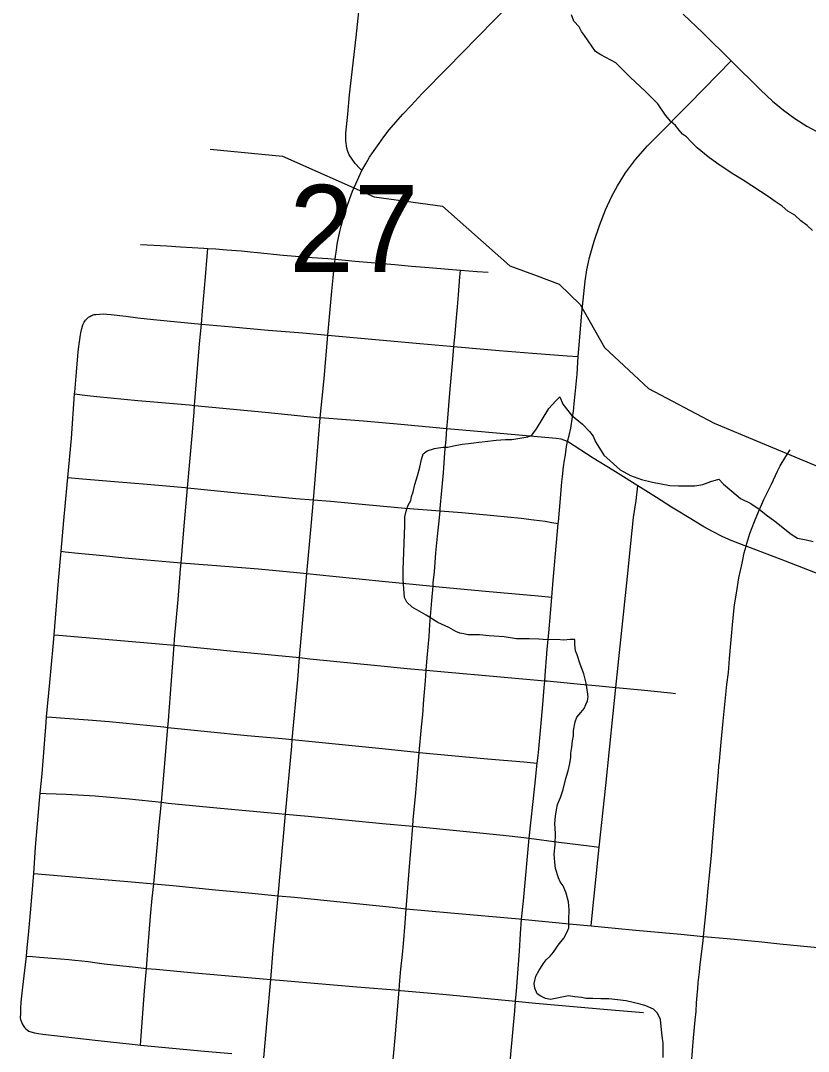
# Model space of a CAD drawing. Extents: x 0 to 34, y 0 to 22.
# Drawn here: x 25.5076 to 25.8867, y 17.7977 to 18.2936 of the extents above; entities that cross this region are included whole.
import ezdxf

# ---------------------------------------------------------------- set-up
doc = ezdxf.new("R2010")
doc.units = 0
for name, color, linetype in [('GM_X_City_Street', 7, 'Continuous'), ('GM_X_County_Road', 7, 'Continuous'), ('GM_X_Minor_River', 7, 'Continuous'), ('GM_X_Section_Text', 7, 'Continuous'), ('GM_X_State_Route', 7, 'Continuous')]:
    doc.layers.add(name, color=color, linetype=linetype)

msp = doc.modelspace()

# ---------------------------------------------------------------- linework, layer by layer
at = {"layer": 'GM_X_City_Street'}
for points in [[(25.67191, 18.22143), (25.67093, 18.22249), (25.66867, 18.22491), (25.66717, 18.22691), (25.66578, 18.22908), (25.66506, 18.2306), (25.66457, 18.23225), (25.6641, 18.23578), (25.66416, 18.23939), (25.66509, 18.24866), (25.66593, 18.25791), (25.66906, 18.28569), (25.67192, 18.31163)], [(25.82646, 18.29676), (25.83585, 18.28782), (25.8495, 18.27426), (25.86365, 18.26028), (25.86951, 18.25479), (25.87473, 18.25047), (25.88024, 18.24651), (25.88599, 18.2429), (25.89084, 18.24021), (25.89695, 18.23724), (25.90205, 18.23509), (25.90852, 18.23263), (25.91338, 18.23115), (25.91735, 18.23022), (25.92275, 18.22896), (25.93676, 18.22625), (25.95878, 18.22236), (25.99119, 18.21664), (26.00773, 18.21385), (26.01995, 18.2121), (26.03122, 18.21093)], [(25.74873, 17.86129), (25.74963, 17.87012), (25.75233, 17.90021), (25.75512, 17.92529), (25.75628, 17.93638), (25.75667, 17.9401), (25.75698, 17.94317), (25.75823, 17.95735), (25.75914, 17.96656), (25.75964, 17.97271), (25.75988, 17.97599), (25.76023, 17.98072), (25.76065, 17.98687), (25.76102, 17.99115), (25.76179, 17.9991), (25.76259, 18.00831), (25.76326, 18.0162), (25.76396, 18.02443), (25.76461, 18.03154), (25.76509, 18.03706), (25.76637, 18.05172), (25.76643, 18.05248), (25.76737, 18.06361), (25.76807, 18.07163), (25.76835, 18.07424), (25.76896, 18.07895), (25.76943, 18.08206), (25.76982, 18.08469), (25.7704, 18.0887), (25.77085, 18.09104), (25.77158, 18.09397), (25.77237, 18.09745), (25.77324, 18.10296), (25.77363, 18.10549), (25.77408, 18.1094), (25.77451, 18.1139), (25.77539, 18.12346), (25.77602, 18.132), (25.77656, 18.13938), (25.77773, 18.15309), (25.77926, 18.16828), (25.78017, 18.17373), (25.78091, 18.17733), (25.78146, 18.17972), (25.78361, 18.18744), (25.78615, 18.19506), (25.7891, 18.20252), (25.79219, 18.20923), (25.79481, 18.21409), (25.79877, 18.22032), (25.80349, 18.22677), (25.80938, 18.23344), (25.81612, 18.24005), (25.82666, 18.25081), (25.8288, 18.25302), (25.83652, 18.26099), (25.8495, 18.27426)], [(25.56535, 18.18587), (25.57808, 18.18527), (25.58466, 18.18484), (25.59021, 18.1845), (25.59577, 18.18416), (25.59771, 18.18405), (25.60158, 18.18382), (25.60688, 18.18339), (25.61389, 18.18279), (25.61833, 18.18236), (25.62162, 18.182), (25.63397, 18.18079), (25.64789, 18.17972), (25.65541, 18.17912), (25.65895, 18.17877), (25.66861, 18.17782), (25.68767, 18.17622), (25.69575, 18.17544), (25.70211, 18.17494), (25.71932, 18.17355), (25.72728, 18.17297), (25.73258, 18.17263)], [(25.5717, 17.87828), (25.57349, 17.89755), (25.57419, 17.90509), (25.57536, 17.91749), (25.57676, 17.93247), (25.57856, 17.95353), (25.57884, 17.95682), (25.58027, 17.9761), (25.58152, 17.99307), (25.58173, 17.99593), (25.58343, 18.01512), (25.58462, 18.02962), (25.58488, 18.03279), (25.58617, 18.04856), (25.58793, 18.06883), (25.5904, 18.09556), (25.59113, 18.10543), (25.59138, 18.10848), (25.59379, 18.13812), (25.59464, 18.14757), (25.59521, 18.15394), (25.59663, 18.17032), (25.59741, 18.18021), (25.59771, 18.18405)], [(25.69324, 17.86627), (25.69496, 17.88853), (25.6955, 17.89602), (25.69634, 17.90595), (25.69659, 17.9091), (25.69776, 17.92209), (25.69857, 17.93166), (25.69946, 17.9415), (25.70056, 17.95358), (25.70112, 17.95954), (25.70172, 17.96703), (25.70245, 17.97587), (25.70285, 17.98105), (25.70331, 17.98706), (25.70417, 17.99725), (25.70461, 18.00302), (25.70551, 18.01458), (25.7061, 18.02145), (25.70624, 18.02306), (25.70673, 18.02844), (25.7075, 18.03749), (25.70831, 18.04561), (25.70904, 18.05274), (25.70948, 18.0577), (25.70958, 18.05879), (25.71039, 18.06753), (25.71111, 18.07602), (25.71183, 18.08559), (25.71237, 18.09226), (25.71277, 18.09723), (25.71318, 18.10228), (25.71355, 18.10633), (25.71391, 18.11058), (25.71454, 18.118), (25.7156, 18.13052), (25.71616, 18.13679), (25.71671, 18.14288), (25.71725, 18.14883), (25.71788, 18.15587), (25.71833, 18.16173), (25.71905, 18.17032), (25.71932, 18.17355)], [(25.53986, 18.15044), (25.54036, 18.15087), (25.54097, 18.1513), (25.54183, 18.1518), (25.54305, 18.15216), (25.54377, 18.15226), (25.54557, 18.15244), (25.54742, 18.15249), (25.54911, 18.15241), (25.55125, 18.15222), (25.55832, 18.15139), (25.56403, 18.15063), (25.5716, 18.14982), (25.59464, 18.14757), (25.60939, 18.14621), (25.62673, 18.14472), (25.64346, 18.14345), (25.65545, 18.14232), (25.66257, 18.14165), (25.69973, 18.13831), (25.71454, 18.13693), (25.71616, 18.13679), (25.72512, 18.13598), (25.73791, 18.13487), (25.75389, 18.13359), (25.7707, 18.13237), (25.77602, 18.132)], [(25.51393, 17.8833), (25.51481, 17.89591), (25.5168, 17.91831), (25.51712, 17.92182), (25.51796, 17.93126), (25.51994, 17.95594), (25.52017, 17.9586), (25.52166, 17.97511), (25.52325, 17.99242), (25.52372, 17.99813), (25.52585, 18.024), (25.5271, 18.03827), (25.5284, 18.05308), (25.53011, 18.07038), (25.53041, 18.07374), (25.53212, 18.09262), (25.53365, 18.11398), (25.53371, 18.11483), (25.53452, 18.12445), (25.53522, 18.13227), (25.53541, 18.1343), (25.53555, 18.13569), (25.53569, 18.13684), (25.53584, 18.13802), (25.53598, 18.13924), (25.53609, 18.14005), (25.53627, 18.14143), (25.53644, 18.14241), (25.53664, 18.14339), (25.53712, 18.1455), (25.53758, 18.14719), (25.53785, 18.14785), (25.53817, 18.1485), (25.53889, 18.14943), (25.53935, 18.14993), (25.53986, 18.15044)], [(25.53365, 18.11398), (25.53991, 18.11326), (25.54425, 18.11277), (25.56408, 18.11086), (25.58888, 18.10873), (25.59138, 18.10848), (25.62538, 18.10515), (25.65181, 18.10254)], [(25.83627, 17.85299), (25.83769, 17.867), (25.83855, 17.87599), (25.839, 17.88079), (25.84011, 17.89185), (25.84065, 17.89848), (25.84218, 17.91755), (25.84341, 17.93193), (25.84368, 17.93501), (25.84387, 17.93721), (25.84405, 17.93927), (25.84473, 17.94639), (25.84573, 17.95656), (25.84751, 17.97414), (25.84821, 17.97998), (25.84883, 17.98671), (25.8503, 18.00465), (25.85118, 18.01251), (25.85205, 18.01817), (25.85331, 18.02549), (25.85482, 18.03262), (25.85579, 18.03746), (25.85672, 18.0408), (25.85705, 18.042), (25.8585, 18.04677), (25.86076, 18.05262), (25.86271, 18.05724), (25.86536, 18.06318), (25.86898, 18.07065), (25.87184, 18.07681), (25.87316, 18.07945), (25.87579, 18.08384), (25.87788, 18.08715)], [(25.53041, 18.07374), (25.53737, 18.07315), (25.55281, 18.07186), (25.56861, 18.07061), (25.5868, 18.06895), (25.58793, 18.06883), (25.61363, 18.06624), (25.64009, 18.06373), (25.64853, 18.06303), (25.65681, 18.06233), (25.67539, 18.06071), (25.69271, 18.05904), (25.70948, 18.0577), (25.71996, 18.05687), (25.73542, 18.05549), (25.74847, 18.05418), (25.7546, 18.05345), (25.76011, 18.05273), (25.76333, 18.05221), (25.76637, 18.05172)], [(25.78214, 17.858), (25.78301, 17.86631), (25.78398, 17.87559), (25.78612, 17.89597), (25.78924, 17.92558), (25.79284, 17.96031), (25.7941, 17.97275), (25.79643, 17.99561), (25.79972, 18.02621), (25.80129, 18.04199), (25.80264, 18.05449), (25.80377, 18.06269), (25.80473, 18.06973)], [(25.5271, 18.03827), (25.5291, 18.03807), (25.53534, 18.03745), (25.54733, 18.03626), (25.55781, 18.03519), (25.56831, 18.03416), (25.57943, 18.0332), (25.58488, 18.03279), (25.59985, 18.03166), (25.62211, 18.02981), (25.64064, 18.0281), (25.64538, 18.02761), (25.65792, 18.02632), (25.68323, 18.02372), (25.7061, 18.02145), (25.7073, 18.02134), (25.73139, 18.01903), (25.75673, 18.01679), (25.76326, 18.0162)], [(25.52372, 17.99813), (25.52599, 17.99794), (25.57808, 17.99341), (25.58152, 17.99307), (25.61176, 17.99014), (25.6419, 17.9871), (25.64679, 17.98661), (25.67933, 17.98328), (25.69359, 17.98187), (25.70285, 17.98105), (25.71167, 17.98026), (25.73683, 17.97808), (25.75988, 17.97599), (25.76102, 17.97589), (25.7771, 17.97439), (25.7861, 17.97351), (25.7941, 17.97275), (25.80627, 17.97164), (25.82038, 17.97022), (25.82285, 17.96988)], [(25.52017, 17.9586), (25.52266, 17.95843), (25.529, 17.95802), (25.54023, 17.95719), (25.55021, 17.95635), (25.57653, 17.95374), (25.57856, 17.95353), (25.61672, 17.94967), (25.63344, 17.94818), (25.63838, 17.94769), (25.68168, 17.94344), (25.69836, 17.9416), (25.69946, 17.9415), (25.73239, 17.93846), (25.74973, 17.93695), (25.75628, 17.93638)], [(25.51712, 17.92182), (25.51995, 17.92174), (25.52952, 17.92142), (25.54345, 17.92059), (25.55988, 17.91913), (25.57536, 17.91749), (25.57861, 17.91714), (25.6021, 17.91486), (25.63177, 17.91209), (25.63514, 17.9118), (25.646, 17.91089), (25.68184, 17.90734), (25.69634, 17.90595), (25.7078, 17.90484), (25.73993, 17.90164), (25.74981, 17.90054), (25.75233, 17.90021), (25.76656, 17.89834), (25.78122, 17.89657), (25.78612, 17.89597)], [(25.50779, 17.8126), (25.50765, 17.81412), (25.50771, 17.81548), (25.5078, 17.81838), (25.50797, 17.82135), (25.50868, 17.82854), (25.5104, 17.8434), (25.51086, 17.84746), (25.51148, 17.85377), (25.51241, 17.86438), (25.51393, 17.8833)], [(25.51393, 17.8833), (25.56293, 17.87914), (25.5717, 17.87828), (25.58086, 17.8774), (25.60135, 17.87544), (25.61735, 17.87388), (25.63161, 17.87257)], [(25.56527, 17.8007), (25.56562, 17.80507), (25.56732, 17.82672), (25.56815, 17.83761), (25.56898, 17.84845), (25.5701, 17.86274), (25.571, 17.87144), (25.5717, 17.87828)], [(25.68643, 17.7885), (25.68752, 17.8006), (25.688, 17.80589), (25.6887, 17.81382), (25.68973, 17.82708), (25.69009, 17.83169), (25.69063, 17.83728), (25.69135, 17.84423), (25.69186, 17.84947), (25.69267, 17.85933), (25.69324, 17.86627)], [(25.74244, 17.78329), (25.74286, 17.78828), (25.74356, 17.79629), (25.74544, 17.81715), (25.74581, 17.82186), (25.7462, 17.8268), (25.74765, 17.8458), (25.74823, 17.85419), (25.74873, 17.86129)], [(25.83052, 17.79203), (25.8315, 17.80412), (25.8323, 17.81275), (25.83265, 17.8169), (25.83293, 17.82094), (25.83315, 17.82457), (25.83348, 17.82787), (25.8337, 17.83083), (25.83425, 17.83589), (25.83464, 17.83947), (25.83601, 17.85084), (25.83627, 17.85299)], [(25.5104, 17.8434), (25.51331, 17.84323), (25.51676, 17.84298), (25.52289, 17.84252), (25.52682, 17.84224), (25.53084, 17.84188), (25.53377, 17.8416), (25.53715, 17.84124), (25.54008, 17.84087), (25.54328, 17.84042), (25.54785, 17.83978), (25.56292, 17.83814), (25.56815, 17.83761), (25.57281, 17.83714), (25.58953, 17.83563), (25.62799, 17.83222), (25.63224, 17.83184), (25.66939, 17.82866), (25.68973, 17.82708), (25.69046, 17.82702), (25.71088, 17.82524), (25.74581, 17.82186), (25.75542, 17.82093), (25.79009, 17.81785), (25.80743, 17.81633)], [(25.50779, 17.8126), (25.50841, 17.81093), (25.50884, 17.81006), (25.50953, 17.80908), (25.51012, 17.80848), (25.51101, 17.80784), (25.5116, 17.80745), (25.51263, 17.80705), (25.51426, 17.80661), (25.51529, 17.80641), (25.51621, 17.80629), (25.51834, 17.80601), (25.54359, 17.80309), (25.5627, 17.80094), (25.56527, 17.8007), (25.59608, 17.79779), (25.60931, 17.79662)]]:
    msp.add_lwpolyline(points, dxfattribs=at)
at = {"layer": 'GM_X_County_Road'}
for points in [[(25.63161, 17.87257), (25.63948, 17.87181), (25.68663, 17.86705), (25.69324, 17.86627)], [(25.69324, 17.86627), (25.71466, 17.86427), (25.74748, 17.86142), (25.74873, 17.86129)], [(25.74873, 17.86129), (25.77344, 17.8588), (25.78214, 17.858)], [(25.78214, 17.858), (25.8019, 17.85618), (25.82542, 17.85405), (25.83627, 17.85299)], [(25.83627, 17.85299), (25.84768, 17.85189), (25.86439, 17.85033), (25.87304, 17.84938), (25.89284, 17.84755), (25.90945, 17.84595)]]:
    msp.add_lwpolyline(points, dxfattribs=at)
at = {"layer": 'GM_X_Minor_River'}
for points in [[(25.88877, 18.19268), (25.88615, 18.195), (25.88315, 18.19733), (25.88016, 18.20004), (25.87678, 18.20199), (25.87415, 18.20431), (25.87078, 18.20665), (25.8674, 18.20898), (25.86364, 18.21132), (25.8595, 18.21405), (25.85537, 18.21678), (25.85086, 18.21951), (25.84673, 18.22223), (25.84259, 18.22496), (25.83847, 18.22807), (25.83322, 18.23233), (25.83023, 18.23542), (25.82799, 18.23774), (25.82611, 18.23891), (25.82462, 18.24083), (25.82276, 18.24314), (25.82051, 18.24508), (25.81791, 18.24816), (25.8142, 18.25354), (25.80822, 18.25971), (25.80111, 18.26629), (25.79401, 18.27324), (25.78686, 18.27716), (25.78422, 18.27872), (25.77903, 18.2864), (25.77754, 18.28833), (25.77644, 18.29062), (25.77383, 18.29332), (25.77274, 18.29638)], [(25.59891, 18.2317), (25.63374, 18.22834), (25.67773, 18.20884), (25.71064, 18.20437), (25.74307, 18.17561), (25.75625, 18.17079), (25.76679, 18.16678), (25.77684, 18.15708), (25.78856, 18.13633), (25.80979, 18.11653), (25.84132, 18.09994), (25.90829, 18.072), (25.94236, 18.06865), (26.00835, 18.04909), (26.02881, 18.04754), (26.07472, 18.02952), (26.08603, 18.02587), (26.12021, 18.00885), (26.21688, 17.94915), (26.25303, 17.93588), (26.28813, 17.92681), (26.38536, 17.91383), (26.4329, 17.90109)], [(25.76112, 17.9956), (25.75696, 17.99605), (25.7524, 17.99612), (25.74633, 17.99622), (25.74027, 17.99708), (25.73307, 17.99757), (25.72852, 17.99803), (25.7251, 17.99808), (25.72282, 17.99812), (25.72093, 17.99853), (25.71904, 17.99894), (25.71715, 17.99973), (25.71377, 18.00168), (25.70849, 18.00405), (25.70285, 18.00756), (25.69608, 18.01147), (25.69346, 18.01379), (25.69236, 18.01609), (25.69205, 18.02028), (25.69174, 18.02484), (25.69181, 18.0294), (25.69253, 18.05067), (25.6926, 18.05485), (25.69341, 18.05826), (25.6942, 18.06053), (25.69538, 18.06279), (25.69579, 18.06468), (25.69658, 18.06695), (25.6974, 18.07036), (25.6986, 18.07452), (25.69981, 18.07868), (25.70063, 18.08247), (25.70143, 18.08511), (25.70335, 18.0866), (25.70679, 18.08769), (25.70869, 18.08804), (25.71097, 18.08838), (25.71325, 18.08835), (25.71592, 18.08906), (25.72011, 18.08975), (25.72315, 18.09008), (25.72581, 18.09042), (25.72809, 18.09077), (25.73114, 18.0911), (25.73646, 18.09177), (25.74102, 18.09208), (25.74406, 18.09203), (25.75167, 18.09343), (25.75358, 18.09415), (25.75591, 18.09716), (25.75864, 18.10167), (25.76176, 18.10694), (25.76523, 18.11069), (25.76716, 18.11256), (25.76863, 18.10911), (25.77271, 18.10373), (25.77796, 18.09946), (25.78132, 18.09599), (25.78318, 18.09368), (25.78428, 18.091), (25.78613, 18.08793), (25.78835, 18.08447), (25.79135, 18.08176), (25.79622, 18.0775), (25.80111, 18.07477), (25.80639, 18.07278), (25.81168, 18.07155), (25.81585, 18.07073), (25.82001, 18.0699), (25.82418, 18.06983), (25.82836, 18.06977), (25.83215, 18.06971), (25.83596, 18.0704), (25.83978, 18.07186), (25.84359, 18.07294), (25.84584, 18.07062), (25.84996, 18.06714), (25.85408, 18.06365), (25.85897, 18.06129), (25.86311, 18.05856), (25.86648, 18.05585), (25.87061, 18.05274), (25.87848, 18.04653), (25.88149, 18.04459), (25.88565, 18.04376), (25.88905, 18.04294)], [(25.81677, 17.79476), (25.81684, 17.79932), (25.81688, 17.8016), (25.81654, 17.80389), (25.8162, 17.80656), (25.81587, 17.8096), (25.81554, 17.81303), (25.81407, 17.8161), (25.81221, 17.81803), (25.80843, 17.81961), (25.80579, 17.82041), (25.80239, 17.82123), (25.79898, 17.82204), (25.79481, 17.82249), (25.79065, 17.82293), (25.78685, 17.823), (25.78305, 17.82306), (25.77964, 17.82311), (25.77775, 17.82352), (25.77434, 17.82396), (25.77131, 17.82439), (25.76255, 17.82263), (25.76028, 17.82305), (25.75802, 17.82422), (25.75614, 17.82539), (25.75504, 17.82807), (25.7547, 17.83036), (25.75551, 17.83377), (25.75707, 17.8364), (25.75902, 17.83979), (25.76057, 17.84167), (25.7625, 17.84354), (25.76405, 17.84541), (25.76638, 17.8488), (25.76909, 17.85217), (25.77066, 17.85519), (25.77145, 17.85708), (25.77151, 17.86088), (25.77159, 17.86582), (25.77127, 17.86962), (25.7702, 17.87382), (25.76873, 17.87727), (25.76725, 17.87919), (25.76652, 17.8811), (25.76507, 17.88569), (25.76474, 17.88874), (25.76442, 17.89254), (25.76487, 17.8971), (25.76496, 17.90242), (25.76466, 17.90736), (25.76509, 17.91078), (25.76552, 17.91381), (25.76594, 17.91646), (25.76751, 17.91986), (25.76871, 17.92364), (25.76993, 17.92894), (25.77113, 17.93272), (25.77195, 17.93613), (25.77238, 17.93917), (25.77241, 17.94107), (25.77283, 17.9441), (25.77326, 17.94713), (25.77368, 17.94941), (25.77372, 17.95207), (25.77454, 17.95624), (25.77534, 17.9585), (25.77727, 17.96075), (25.77882, 17.96263), (25.77961, 17.96452), (25.7804, 17.9664), (25.78081, 17.9683), (25.78047, 17.97058), (25.77978, 17.97478), (25.77871, 17.97935), (25.77688, 17.98394), (25.77544, 17.98853), (25.77471, 17.99044), (25.77438, 17.99349), (25.77441, 17.99577), (25.77214, 17.9958), (25.7691, 17.99547), (25.76568, 17.99591), (25.76112, 17.9956)]]:
    msp.add_lwpolyline(points, dxfattribs=at)
at = {"layer": 'GM_X_State_Route'}
for points in [[(25.67191, 18.22143), (25.67387, 18.22498), (25.6756, 18.22787), (25.6777, 18.23108), (25.68011, 18.23456), (25.68238, 18.23773), (25.68505, 18.24102), (25.68823, 18.24477), (25.69158, 18.24856), (25.69551, 18.25284), (25.70094, 18.25856), (25.71283, 18.27072), (25.72748, 18.2856), (25.76865, 18.32788), (25.78201, 18.34146)], [(25.65895, 18.17877), (25.65914, 18.18031), (25.65957, 18.18313), (25.66002, 18.186), (25.66061, 18.18911), (25.66125, 18.19211), (25.66193, 18.19478), (25.66267, 18.19774), (25.6637, 18.20113), (25.66476, 18.20441), (25.66608, 18.20806), (25.66735, 18.21149), (25.66888, 18.21504), (25.67036, 18.21825), (25.67191, 18.22143)], [(25.65545, 18.14232), (25.65734, 18.16347), (25.65797, 18.16988), (25.65846, 18.17475), (25.65879, 18.1775), (25.65895, 18.17877)], [(25.65181, 18.10254), (25.65365, 18.12139), (25.65545, 18.14232)], [(25.62468, 17.7946), (25.62631, 17.81273), (25.62799, 17.83222), (25.6294, 17.84856), (25.63161, 17.87257), (25.63514, 17.9118), (25.63808, 17.94445), (25.63838, 17.94769), (25.64101, 17.97654), (25.6419, 17.9871), (25.64454, 18.0182), (25.64538, 18.02761), (25.64744, 18.05041), (25.64853, 18.06303), (25.65021, 18.08265), (25.65181, 18.10254)], [(25.85583, 18.04114), (25.8496, 18.04353), (25.84558, 18.04527), (25.84058, 18.04785), (25.83642, 18.05005), (25.82928, 18.05434), (25.82406, 18.05758), (25.82088, 18.05949), (25.8136, 18.06417), (25.80473, 18.06973), (25.79525, 18.07567), (25.79269, 18.07731), (25.78318, 18.08309), (25.77085, 18.09104), (25.76768, 18.09215), (25.76529, 18.0926), (25.7239, 18.09622), (25.71277, 18.09723), (25.69055, 18.09925), (25.67264, 18.10088), (25.65181, 18.10254)], [(25.89311, 18.02676), (25.8757, 18.03346), (25.85672, 18.0408), (25.85583, 18.04114)]]:
    msp.add_lwpolyline(points, dxfattribs=at)

# ---------------------------------------------------------------- texts
at = {"layer": 'GM_X_Section_Text'}
msp.add_text('27', height=0.041856, rotation=0, dxfattribs=at).set_placement((25.63691, 18.17269))

doc.saveas('drawing.dxf')
